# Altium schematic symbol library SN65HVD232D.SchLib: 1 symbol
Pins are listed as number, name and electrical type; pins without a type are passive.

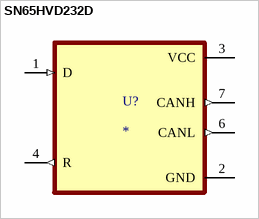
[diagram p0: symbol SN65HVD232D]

## SN65HVD232D
designator U?
3.3 V CAN Transceiver; MP: SN65HVD232D; MF: Texas Instruments
footprint SN65HVD232D
pins: 1 D (in), 2 GND (power), 3 VCC (power), 4 R (out), 6 CANL (out), 7 CANH (out)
